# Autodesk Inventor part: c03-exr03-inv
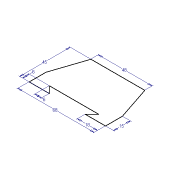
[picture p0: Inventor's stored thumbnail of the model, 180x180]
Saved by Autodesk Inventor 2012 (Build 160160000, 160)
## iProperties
Shininess: 64.0
Length Units: 11269
Angle Units: 11279
Time Units: 11290
Mass Units: 11283
Length Display Precision: 3
Angle Display Precision: 2
Compacted: True
Created: 2002-02
Part Number: c03-exr03-inv
Document SubType Name: Modeling
Density: 1 g/cm^3
Material: Default
Density: 0.0
Volumn: 0.0
Area: 0.0
PropertySet Name: Model Information
Control State: 0
Master: False
Checked Out: False
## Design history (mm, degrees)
sketch "Sketch1"
  geometry: L1 (-37.52, -4.549)-(-37.52, -19.549); L2 (-37.52, -19.549)-(-19.52, -19.549); L3 (-19.52, -19.549)-(-25.52, -13.549); L4 (-25.52, -13.549)-(18.48, -13.549); L5 (18.48, -13.549)-(12.48, -19.549); L6 (12.48, -19.549)-(30.48, -19.549); L7 (30.48, -19.549)-(30.48, -4.549); L8 (30.48, -4.549)-(20.48, 25.451); L9 (20.48, 25.451)-(-27.52, 25.451); L10 (-27.52, 25.451)-(-37.52, -4.549)
  constraints: 20 end point, 4 equal length, 2 parallel, 2 perpendicular, 1 collinear, 1 horizontal, 1 vertical
  dimensions: "d0" = 18 distance of L5.end L6.end; "d1" = 6 horizontal distance of L2.end L3.end; "d2" = 68 distance between parallel lines of L7 L1; "d3" = 6 horizontal distance of L2.end L3.end; "d4" = 45 distance between parallel lines of L9 L2; "d5" = 15 distance of L6.end L7.end; "d6" = 48 distance of L8.end L9.end
